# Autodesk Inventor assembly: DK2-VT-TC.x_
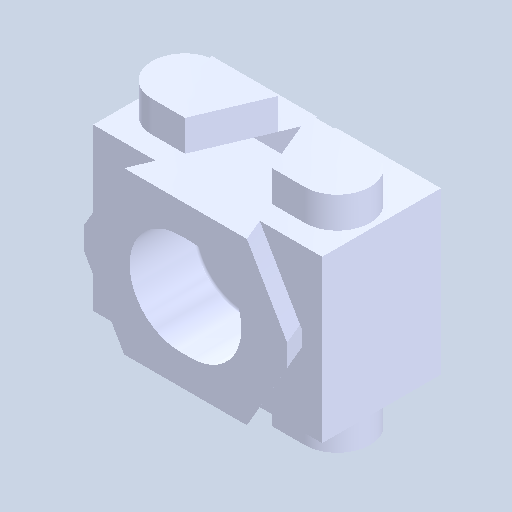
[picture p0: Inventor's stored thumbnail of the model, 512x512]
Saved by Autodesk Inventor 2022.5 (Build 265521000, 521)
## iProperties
Created: 2024-05
Part Number: DK2-VT-TC.x_
Document SubType Name: Assembly
Designer: ImaoCorp
Author: ImaoCorp
Sending System: SOLIDWORKS 2022-2022290
MC: AMD64
MC_MODEL: Intel64 Family 6 Model 60 Stepping 3, GenuineIntel
OS: Windows_NT
FRU: Parasolid Version 33.1, build 260,  4-25-2022
FORMAT: text
GUISE: transmit
KEY: FILEDK2-VT-TC.x_t
DATE: Mon May 20 16:29:33 2024
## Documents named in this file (4)
- X:\14_SW2022-Inv2022\保留中\ok-vise\データ\dk2-vt-tc\DK2-VT-TC.x_.iam
- X:\14_SW2022-Inv2022\保留中\ok-vise\データ\dk2-vt-tc\DK2-VT-TC_01.ipt
- X:\14_SW2022-Inv2022\保留中\ok-vise\データ\dk2-vt-tc\DK2-VT-TC_02.ipt
- X:\14_SW2022-Inv2022\保留中\ok-vise\データ\dk2-vt-tc\DK2-VT-TC_03.ipt
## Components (3 placed, 3 different names)
1. DK2-VT-TC_01
2. DK2-VT-TC_02
3. DK2-VT-TC_03
